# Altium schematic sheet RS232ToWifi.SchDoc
size A4; CheckedBy: Everyone how cares; DocumentNumber: 1; SheetNumber: 1; SheetTotal: 4
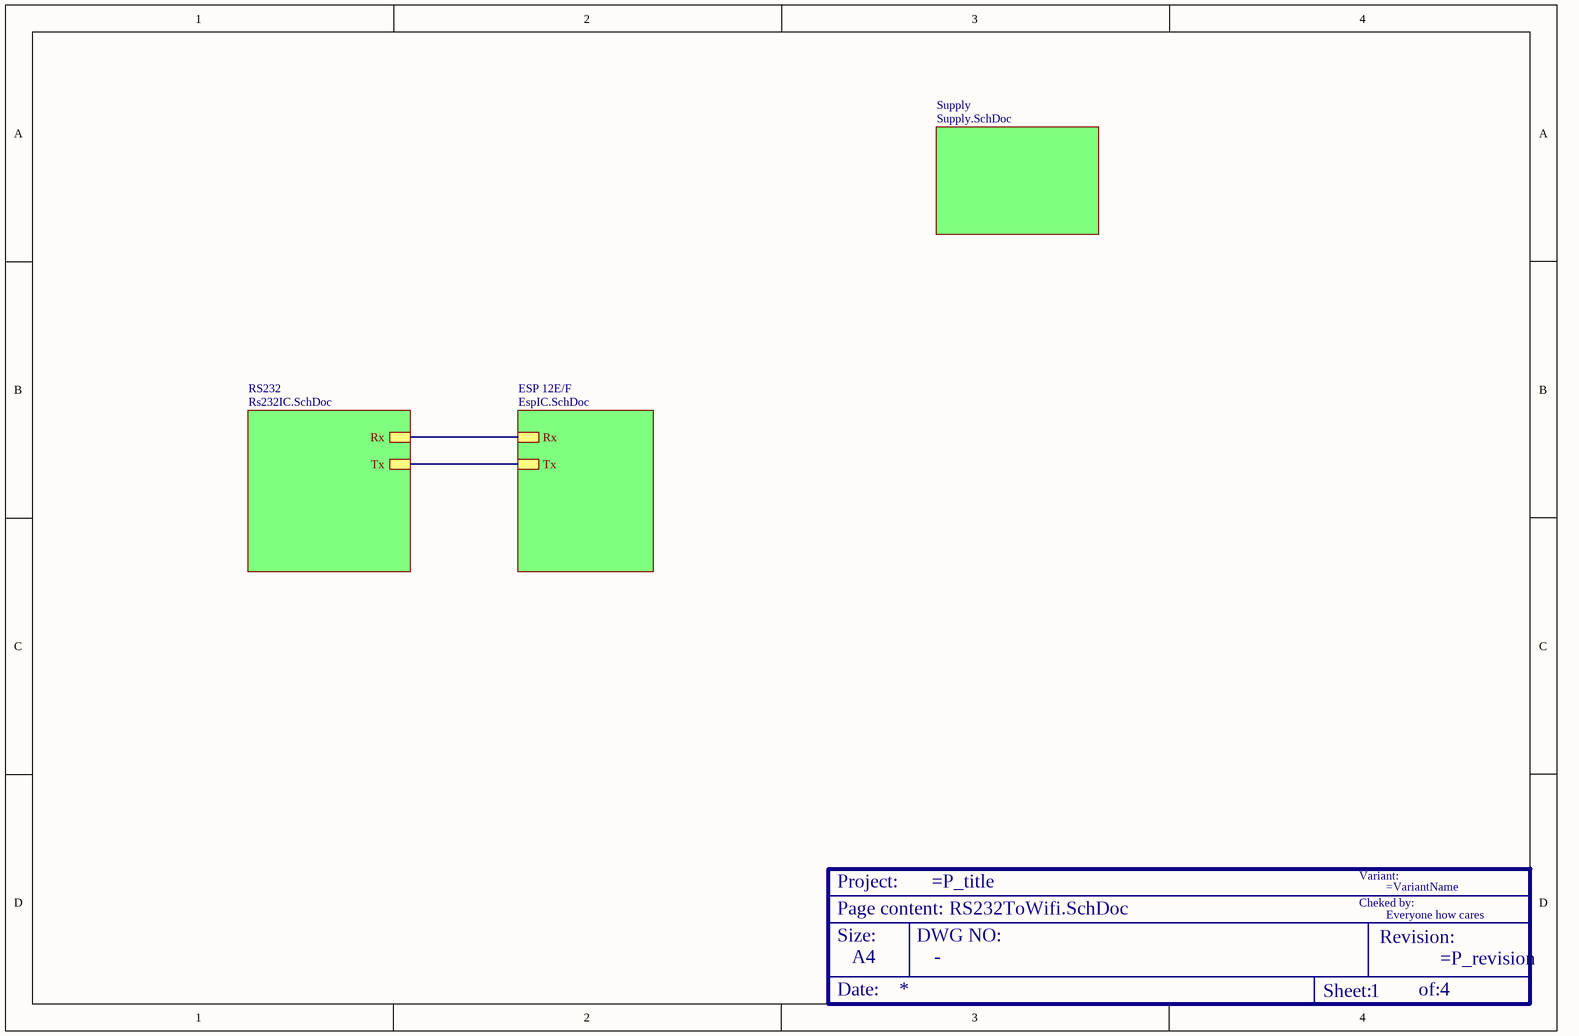
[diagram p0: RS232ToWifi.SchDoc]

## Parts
?  Size: A4  (hidden comment: TitleBox)  (graphical)

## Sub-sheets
ESP 12E/F = EspIC.SchDoc: Tx, Rx
RS232 = Rs232IC.SchDoc: Rx, Tx
Supply = Supply.SchDoc: no entries

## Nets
(unnamed): sheet RS232/Rx, sheet ESP 12E/F/Rx
(unnamed): sheet RS232/Tx, sheet ESP 12E/F/Tx  [a separate net that carries the same name]

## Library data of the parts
? = TitleBox_1: coordenadas: (610;20) Size A4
